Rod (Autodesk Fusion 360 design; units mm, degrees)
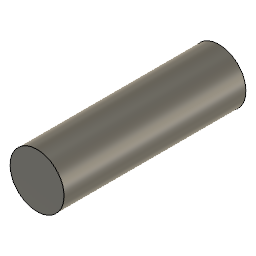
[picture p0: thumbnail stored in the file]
part number: 2026-03-20-15-56-08-521
sketch "Sketch1" plane through (0, 0, 0) normal (0, 1, 0) x axis (1, 0, 0)
  circle C1 centre (0, 0) radius 3.7719
  point P1 (0, 0)
  point P2 (0, 0)
  coincident P1 P2
  dimension "d1" diameter C1 = 7.5438
extrude "Extrude1" new body sketch "Sketch1" along normal blind 25.4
